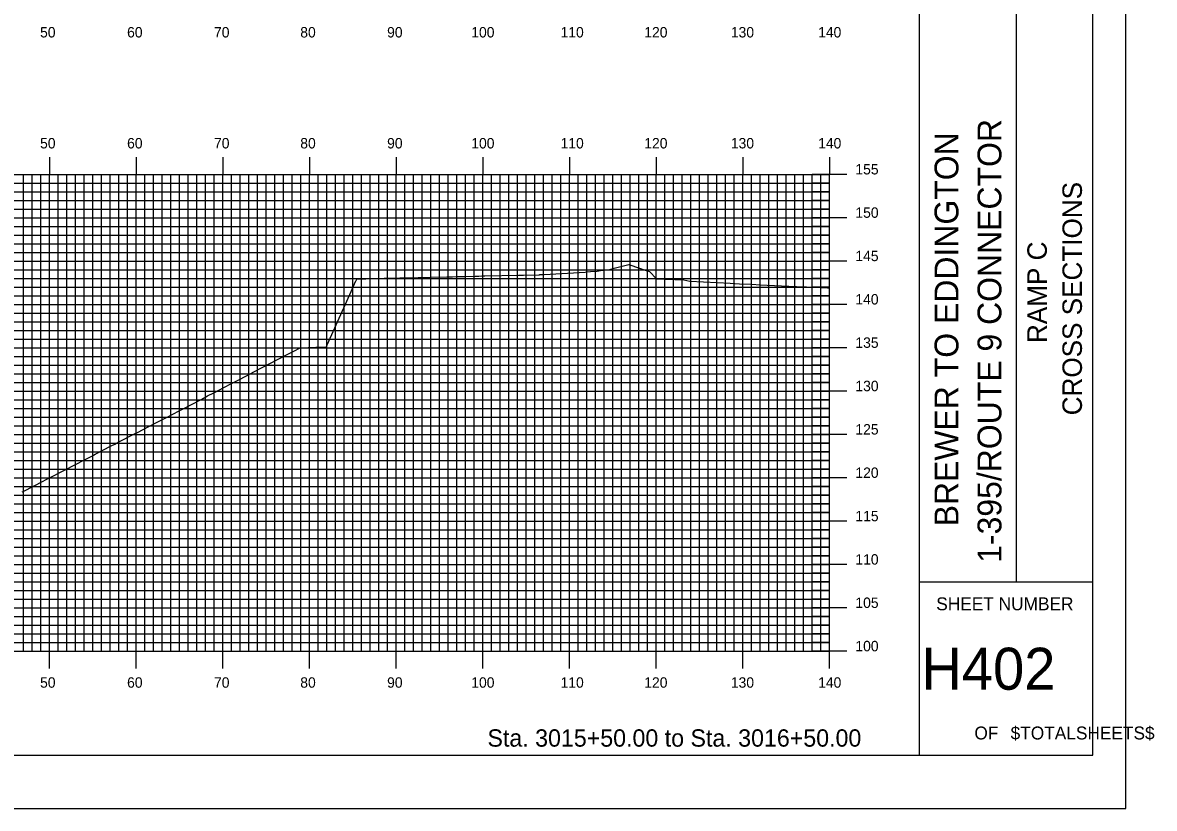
# Model space of a CAD drawing. Extents: x 1685192 to 1685536, y 461260 to 461480.
# Drawn here: x 1685405.1 to 1685535.7, y 461260 to 461350.6 of the extents above; entities that cross this region are included whole.
import ezdxf

# ---------------------------------------------------------------- set-up
doc = ezdxf.new("R2010")
doc.units = 0
for name, color, linetype in [('BORDER', 7, 'Continuous'), ('H_V ANNOTATION', 7, 'Continuous'), ('MAJOR', 7, 'Continuous'), ('MINOR', 7, 'Continuous'), ('PLOT BOUNDARY', 7, 'Continuous'), ('S_Roadway_Centerline', 7, 'Continuous')]:
    doc.layers.add(name, color=color, linetype=linetype)

msp = doc.modelspace()

# ---------------------------------------------------------------- linework, layer by layer
at = {"layer": 'BORDER'}
for p, q in [((1685508.63, 461266.07), (1685508.63, 461476.07)), ((1685519.81, 461286.08), (1685519.81, 461356.08)), ((1685508.63, 461286.08), (1685528.63, 461286.08))]:
    msp.add_line(p, q, dxfattribs=at)
msp.add_lwpolyline([(1685208.63, 461266.07), (1685528.63, 461266.07), (1685528.63, 461476.07), (1685208.63, 461476.07)], close=True, dxfattribs=at)
at = {"layer": 'MAJOR'}
for p, q in [((1685408.23, 461335.08), (1685408.23, 461333.07)), ((1685418.23, 461335.08), (1685418.23, 461333.07)), ((1685428.23, 461335.08), (1685428.23, 461333.07)), ((1685438.23, 461335.08), (1685438.23, 461333.07)), ((1685448.23, 461335.08), (1685448.23, 461333.07)), ((1685458.23, 461335.08), (1685458.23, 461333.07)), ((1685468.23, 461335.08), (1685468.23, 461333.07)), ((1685478.23, 461335.08), (1685478.23, 461333.07)), ((1685488.23, 461335.08), (1685488.23, 461333.07)), ((1685498.23, 461335.08), (1685498.23, 461333.07)), ((1685218.23, 461333.07), (1685498.23, 461333.07)), ((1685218.23, 461333.07), (1685498.23, 461333.07)), ((1685408.23, 461278.07), (1685408.23, 461333.07)), ((1685418.23, 461278.07), (1685418.23, 461333.07)), ((1685428.23, 461278.07), (1685428.23, 461333.07)), ((1685438.23, 461278.07), (1685438.23, 461333.07)), ((1685448.23, 461278.07), (1685448.23, 461333.07)), ((1685458.23, 461278.07), (1685458.23, 461333.07)), ((1685468.23, 461278.07), (1685468.23, 461333.07)), ((1685478.23, 461278.07), (1685478.23, 461333.07)), ((1685488.23, 461278.07), (1685488.23, 461333.07)), ((1685500.23, 461333.07), (1685496.23, 461333.07)), ((1685498.23, 461278.07), (1685498.23, 461333.07)), ((1685498.23, 461278.07), (1685498.23, 461333.07)), ((1685218.23, 461328.07), (1685498.23, 461328.07)), ((1685500.23, 461328.07), (1685496.23, 461328.07)), ((1685218.23, 461323.07), (1685498.23, 461323.07)), ((1685500.23, 461323.07), (1685496.23, 461323.07)), ((1685218.23, 461318.07), (1685498.23, 461318.07)), ((1685500.23, 461318.07), (1685496.23, 461318.07)), ((1685218.23, 461313.07), (1685498.23, 461313.07)), ((1685500.23, 461313.07), (1685496.23, 461313.07)), ((1685218.23, 461308.07), (1685498.23, 461308.07)), ((1685500.23, 461308.07), (1685496.23, 461308.07)), ((1685218.23, 461303.07), (1685498.23, 461303.07)), ((1685500.23, 461303.07), (1685496.23, 461303.07)), ((1685218.23, 461298.07), (1685498.23, 461298.07)), ((1685500.23, 461298.07), (1685496.23, 461298.07)), ((1685218.23, 461293.07), (1685498.23, 461293.07)), ((1685500.23, 461293.07), (1685496.23, 461293.07)), ((1685218.23, 461288.07), (1685498.23, 461288.07)), ((1685500.23, 461288.07), (1685496.23, 461288.07)), ((1685218.23, 461283.07), (1685498.23, 461283.07)), ((1685500.23, 461283.07), (1685496.23, 461283.07)), ((1685218.23, 461278.07), (1685498.23, 461278.07)), ((1685218.23, 461278.07), (1685498.23, 461278.07)), ((1685408.23, 461276.07), (1685408.23, 461278.07)), ((1685418.23, 461276.07), (1685418.23, 461278.07)), ((1685428.23, 461276.07), (1685428.23, 461278.07)), ((1685438.23, 461276.07), (1685438.23, 461278.07)), ((1685448.23, 461276.07), (1685448.23, 461278.07)), ((1685458.23, 461276.07), (1685458.23, 461278.07)), ((1685468.23, 461276.07), (1685468.23, 461278.07)), ((1685478.23, 461276.07), (1685478.23, 461278.07)), ((1685488.23, 461276.07), (1685488.23, 461278.07)), ((1685500.23, 461278.07), (1685496.23, 461278.07)), ((1685498.23, 461276.07), (1685498.23, 461278.07))]:
    msp.add_line(p, q, dxfattribs=at)
at = {"layer": 'MINOR'}
for p, q in [((1685405.23, 461278.07), (1685405.23, 461333.07)), ((1685406.23, 461278.07), (1685406.23, 461333.07)), ((1685407.23, 461278.07), (1685407.23, 461333.07)), ((1685409.23, 461278.07), (1685409.23, 461333.07)), ((1685410.23, 461278.07), (1685410.23, 461333.07)), ((1685411.23, 461278.07), (1685411.23, 461333.07)), ((1685412.23, 461278.07), (1685412.23, 461333.07)), ((1685413.23, 461278.07), (1685413.23, 461333.07)), ((1685414.23, 461278.07), (1685414.23, 461333.07)), ((1685415.23, 461278.07), (1685415.23, 461333.07)), ((1685416.23, 461278.07), (1685416.23, 461333.07)), ((1685417.23, 461278.07), (1685417.23, 461333.07)), ((1685419.23, 461278.07), (1685419.23, 461333.07)), ((1685420.23, 461278.07), (1685420.23, 461333.07)), ((1685421.23, 461278.07), (1685421.23, 461333.07)), ((1685422.23, 461278.07), (1685422.23, 461333.07)), ((1685423.23, 461278.07), (1685423.23, 461333.07)), ((1685424.23, 461278.07), (1685424.23, 461333.07)), ((1685425.23, 461278.07), (1685425.23, 461333.07)), ((1685426.23, 461278.07), (1685426.23, 461333.07)), ((1685427.23, 461278.07), (1685427.23, 461333.07)), ((1685429.23, 461278.07), (1685429.23, 461333.07)), ((1685430.23, 461278.07), (1685430.23, 461333.07)), ((1685431.23, 461278.07), (1685431.23, 461333.07)), ((1685432.23, 461278.07), (1685432.23, 461333.07)), ((1685433.23, 461278.07), (1685433.23, 461333.07)), ((1685434.23, 461278.07), (1685434.23, 461333.07)), ((1685435.23, 461278.07), (1685435.23, 461333.07)), ((1685436.23, 461278.07), (1685436.23, 461333.07)), ((1685437.23, 461278.07), (1685437.23, 461333.07)), ((1685439.23, 461278.07), (1685439.23, 461333.07)), ((1685440.23, 461278.07), (1685440.23, 461333.07)), ((1685441.23, 461278.07), (1685441.23, 461333.07)), ((1685442.23, 461278.07), (1685442.23, 461333.07)), ((1685443.23, 461278.07), (1685443.23, 461333.07)), ((1685444.23, 461278.07), (1685444.23, 461333.07)), ((1685445.23, 461278.07), (1685445.23, 461333.07)), ((1685446.23, 461278.07), (1685446.23, 461333.07)), ((1685447.23, 461278.07), (1685447.23, 461333.07)), ((1685449.23, 461278.07), (1685449.23, 461333.07)), ((1685450.23, 461278.07), (1685450.23, 461333.07)), ((1685451.23, 461278.07), (1685451.23, 461333.07)), ((1685452.23, 461278.07), (1685452.23, 461333.07)), ((1685453.23, 461278.07), (1685453.23, 461333.07)), ((1685454.23, 461278.07), (1685454.23, 461333.07)), ((1685455.23, 461278.07), (1685455.23, 461333.07)), ((1685456.23, 461278.07), (1685456.23, 461333.07)), ((1685457.23, 461278.07), (1685457.23, 461333.07)), ((1685459.23, 461278.07), (1685459.23, 461333.07)), ((1685460.23, 461278.07), (1685460.23, 461333.07)), ((1685461.23, 461278.07), (1685461.23, 461333.07)), ((1685462.23, 461278.07), (1685462.23, 461333.07)), ((1685463.23, 461278.07), (1685463.23, 461333.07)), ((1685464.23, 461278.07), (1685464.23, 461333.07)), ((1685465.23, 461278.07), (1685465.23, 461333.07)), ((1685466.23, 461278.07), (1685466.23, 461333.07)), ((1685467.23, 461278.07), (1685467.23, 461333.07)), ((1685469.23, 461278.07), (1685469.23, 461333.07)), ((1685470.23, 461278.07), (1685470.23, 461333.07)), ((1685471.23, 461278.07), (1685471.23, 461333.07)), ((1685472.23, 461278.07), (1685472.23, 461333.07)), ((1685473.23, 461278.07), (1685473.23, 461333.07)), ((1685474.23, 461278.07), (1685474.23, 461333.07)), ((1685475.23, 461278.07), (1685475.23, 461333.07)), ((1685476.23, 461278.07), (1685476.23, 461333.07)), ((1685477.23, 461278.07), (1685477.23, 461333.07)), ((1685479.23, 461278.07), (1685479.23, 461333.07)), ((1685480.23, 461278.07), (1685480.23, 461333.07)), ((1685481.23, 461278.07), (1685481.23, 461333.07)), ((1685482.23, 461278.07), (1685482.23, 461333.07)), ((1685483.23, 461278.07), (1685483.23, 461333.07)), ((1685484.23, 461278.07), (1685484.23, 461333.07)), ((1685485.23, 461278.07), (1685485.23, 461333.07)), ((1685486.23, 461278.07), (1685486.23, 461333.07)), ((1685487.23, 461278.07), (1685487.23, 461333.07)), ((1685489.23, 461278.07), (1685489.23, 461333.07)), ((1685490.23, 461278.07), (1685490.23, 461333.07)), ((1685491.23, 461278.07), (1685491.23, 461333.07)), ((1685492.23, 461278.07), (1685492.23, 461333.07)), ((1685493.23, 461278.07), (1685493.23, 461333.07)), ((1685494.23, 461278.07), (1685494.23, 461333.07)), ((1685495.23, 461278.07), (1685495.23, 461333.07)), ((1685496.23, 461278.07), (1685496.23, 461333.07)), ((1685497.23, 461278.07), (1685497.23, 461333.07)), ((1685218.23, 461332.07), (1685498.23, 461332.07)), ((1685218.23, 461331.07), (1685498.23, 461331.07)), ((1685498.23, 461332.07), (1685496.23, 461332.07)), ((1685498.23, 461331.07), (1685496.23, 461331.07)), ((1685218.23, 461330.07), (1685498.23, 461330.07)), ((1685498.23, 461330.07), (1685496.23, 461330.07)), ((1685218.23, 461329.07), (1685498.23, 461329.07)), ((1685498.23, 461329.07), (1685496.23, 461329.07)), ((1685218.23, 461327.07), (1685498.23, 461327.07)), ((1685498.23, 461327.07), (1685496.23, 461327.07)), ((1685218.23, 461326.07), (1685498.23, 461326.07)), ((1685498.23, 461326.07), (1685496.23, 461326.07)), ((1685218.23, 461325.07), (1685498.23, 461325.07)), ((1685498.23, 461325.07), (1685496.23, 461325.07)), ((1685218.23, 461324.07), (1685498.23, 461324.07)), ((1685498.23, 461324.07), (1685496.23, 461324.07)), ((1685218.23, 461322.07), (1685498.23, 461322.07)), ((1685498.23, 461322.07), (1685496.23, 461322.07)), ((1685218.23, 461321.07), (1685498.23, 461321.07)), ((1685498.23, 461321.07), (1685496.23, 461321.07)), ((1685218.23, 461320.07), (1685498.23, 461320.07)), ((1685498.23, 461320.07), (1685496.23, 461320.07)), ((1685218.23, 461319.07), (1685498.23, 461319.07)), ((1685498.23, 461319.07), (1685496.23, 461319.07)), ((1685218.23, 461317.07), (1685498.23, 461317.07)), ((1685498.23, 461317.07), (1685496.23, 461317.07)), ((1685218.23, 461316.07), (1685498.23, 461316.07)), ((1685498.23, 461316.07), (1685496.23, 461316.07)), ((1685218.23, 461315.07), (1685498.23, 461315.07)), ((1685218.23, 461314.07), (1685498.23, 461314.07)), ((1685498.23, 461315.07), (1685496.23, 461315.07)), ((1685498.23, 461314.07), (1685496.23, 461314.07)), ((1685218.23, 461312.07), (1685498.23, 461312.07)), ((1685498.23, 461312.07), (1685496.23, 461312.07)), ((1685218.23, 461311.07), (1685498.23, 461311.07)), ((1685218.23, 461310.07), (1685498.23, 461310.07)), ((1685498.23, 461311.07), (1685496.23, 461311.07)), ((1685498.23, 461310.07), (1685496.23, 461310.07)), ((1685218.23, 461309.07), (1685498.23, 461309.07)), ((1685498.23, 461309.07), (1685496.23, 461309.07)), ((1685218.23, 461307.07), (1685498.23, 461307.07)), ((1685218.23, 461306.07), (1685498.23, 461306.07)), ((1685498.23, 461307.07), (1685496.23, 461307.07)), ((1685498.23, 461306.07), (1685496.23, 461306.07)), ((1685218.23, 461305.07), (1685498.23, 461305.07)), ((1685498.23, 461305.07), (1685496.23, 461305.07)), ((1685218.23, 461304.07), (1685498.23, 461304.07)), ((1685498.23, 461304.07), (1685496.23, 461304.07)), ((1685218.23, 461302.07), (1685498.23, 461302.07)), ((1685218.23, 461301.07), (1685498.23, 461301.07)), ((1685498.23, 461302.07), (1685496.23, 461302.07)), ((1685498.23, 461301.07), (1685496.23, 461301.07)), ((1685218.23, 461300.07), (1685498.23, 461300.07)), ((1685498.23, 461300.07), (1685496.23, 461300.07)), ((1685218.23, 461299.07), (1685498.23, 461299.07)), ((1685498.23, 461299.07), (1685496.23, 461299.07)), ((1685218.23, 461297.07), (1685498.23, 461297.07)), ((1685498.23, 461297.07), (1685496.23, 461297.07)), ((1685218.23, 461296.07), (1685498.23, 461296.07)), ((1685498.23, 461296.07), (1685496.23, 461296.07)), ((1685218.23, 461295.07), (1685498.23, 461295.07)), ((1685498.23, 461295.07), (1685496.23, 461295.07)), ((1685218.23, 461294.07), (1685498.23, 461294.07)), ((1685498.23, 461294.07), (1685496.23, 461294.07)), ((1685218.23, 461292.07), (1685498.23, 461292.07)), ((1685498.23, 461292.07), (1685496.23, 461292.07)), ((1685218.23, 461291.07), (1685498.23, 461291.07)), ((1685498.23, 461291.07), (1685496.23, 461291.07)), ((1685218.23, 461290.07), (1685498.23, 461290.07)), ((1685498.23, 461290.07), (1685496.23, 461290.07)), ((1685218.23, 461289.07), (1685498.23, 461289.07)), ((1685498.23, 461289.07), (1685496.23, 461289.07)), ((1685218.23, 461287.07), (1685498.23, 461287.07)), ((1685498.23, 461287.07), (1685496.23, 461287.07)), ((1685218.23, 461286.07), (1685498.23, 461286.07)), ((1685498.23, 461286.07), (1685496.23, 461286.07)), ((1685218.23, 461285.07), (1685498.23, 461285.07)), ((1685218.23, 461284.07), (1685498.23, 461284.07)), ((1685498.23, 461285.07), (1685496.23, 461285.07)), ((1685498.23, 461284.07), (1685496.23, 461284.07)), ((1685218.23, 461282.07), (1685498.23, 461282.07)), ((1685498.23, 461282.07), (1685496.23, 461282.07)), ((1685218.23, 461281.07), (1685498.23, 461281.07)), ((1685218.23, 461280.07), (1685498.23, 461280.07)), ((1685498.23, 461281.07), (1685496.23, 461281.07)), ((1685498.23, 461280.07), (1685496.23, 461280.07)), ((1685218.23, 461279.07), (1685498.23, 461279.07)), ((1685498.23, 461279.07), (1685496.23, 461279.07))]:
    msp.add_line(p, q, dxfattribs=at)
at = {"layer": 'PLOT BOUNDARY'}
msp.add_lwpolyline([(1685192.44, 461259.95), (1685532.44, 461259.95), (1685532.44, 461479.95), (1685192.44, 461479.95)], close=True, dxfattribs=at)
at = {"layer": 'S_Roadway_Centerline'}
msp.add_lwpolyline([(1685405.09, 461296.45), (1685405.27, 461296.54), (1685407.53, 461297.7), (1685407.77, 461297.83), (1685408.02, 461297.96), (1685410.14, 461299.05), (1685410.44, 461299.21), (1685410.77, 461299.37), (1685412.75, 461300.4), (1685413.12, 461300.59), (1685413.51, 461300.79), (1685415.36, 461301.75), (1685415.8, 461301.97), (1685416.25, 461302.21), (1685417.97, 461303.1), (1685418.47, 461303.36), (1685418.99, 461303.63), (1685420.59, 461304.45), (1685421.14, 461304.74), (1685421.73, 461305.04), (1685423.2, 461305.81), (1685423.82, 461306.13), (1685424.46, 461306.46), (1685425.82, 461307.16), (1685426.49, 461307.52), (1685427.19, 461307.88), (1685428.43, 461308.52), (1685429.16, 461308.9), (1685429.93, 461309.3), (1685431.05, 461309.88), (1685431.83, 461310.29), (1685435.6, 461312.25), (1685436.43, 461312.69), (1685437.18, 461313.07), (1685438.99, 461313.13), (1685440.19, 461313.17), (1685440.26, 461313.32), (1685440.29, 461313.4), (1685442.9, 461319.21), (1685443.61, 461320.79), (1685443.64, 461320.85), (1685443.71, 461321.01), (1685443.87, 461321.02), (1685444.76, 461321.04), (1685445.14, 461321.05), (1685445.79, 461321.06), (1685445.94, 461321.07), (1685446.86, 461321.09), (1685447.81, 461321.11), (1685448.67, 461321.13), (1685449.14, 461321.14), (1685450.01, 461321.16), (1685450.8, 461321.18), (1685451.5, 461321.2), (1685452.15, 461321.21), (1685454.09, 461321.26), (1685454.73, 461321.27), (1685455.3, 461321.29), (1685455.82, 461321.3), (1685456.04, 461321.31), (1685456.28, 461321.31), (1685457.37, 461321.34), (1685457.78, 461321.35), (1685458.14, 461321.36), (1685458.47, 461321.36), (1685462.37, 461321.46), (1685462.53, 461321.46), (1685462.68, 461321.46), (1685462.81, 461321.47), (1685462.93, 461321.47), (1685464.72, 461321.51), (1685464.75, 461321.51), (1685464.78, 461321.51), (1685464.8, 461321.51), (1685464.82, 461321.52), (1685465.31, 461321.53), (1685470.05, 461321.8), (1685470.22, 461321.83), (1685470.66, 461321.86), (1685471.42, 461321.9), (1685471.84, 461322), (1685472.77, 461322.06), (1685473.41, 461322.25), (1685475.08, 461322.68), (1685475.33, 461322.59), (1685476.98, 461322.03), (1685477.49, 461321.88), (1685478.27, 461321.04), (1685481.45, 461320.91), (1685482.14, 461320.75), (1685485.27, 461320.59), (1685486.77, 461320.52), (1685487.84, 461320.47), (1685489.27, 461320.4), (1685490.23, 461320.35), (1685492.71, 461320.23), (1685494.44, 461320.15), (1685495.6, 461320.09), (1685498.02, 461319.98), (1685498.23, 461319.97)], dxfattribs=at)

# ---------------------------------------------------------------- texts
at = {"layer": 'BORDER'}
for s, height, p in [('1-395/ROUTE 9 CONNECTOR', 2.7557, (1685518.08, 461288.27)), ('BREWER TO EDDINGTON', 2.7557, (1685513.12, 461292.48)), ('CROSS SECTIONS', 2.25, (1685527.37, 461305.29)), ('RAMP C', 2.25, (1685523.32, 461313.63))]:
    msp.add_text(s, height=height, rotation=90, dxfattribs=at).set_placement(p)
for s, height, p in [('SHEET NUMBER', 1.4905, (1685510.56, 461282.8)), ('H402', 4.839, (1685508.84, 461273.64)), ('$TOTALSHEETS$', 1.4905, (1685519.14, 461267.9)), ('OF', 1.491, (1685514.96, 461267.9))]:
    msp.add_text(s, height=height, dxfattribs=at).set_placement(p)
at = {"layer": 'H_V ANNOTATION'}
for s, height, p in [('50', 1.2, (1685407.16, 461348.87)), ('60', 1.2, (1685417.2, 461348.87)), ('70', 1.2, (1685427.23, 461348.87)), ('80', 1.2, (1685437.18, 461348.87)), ('90', 1.2, (1685447.2, 461348.87)), ('100', 1.2, (1685456.91, 461348.87)), ('110', 1.2, (1685467.21, 461348.87)), ('120', 1.2, (1685476.87, 461348.87)), ('130', 1.2, (1685486.86, 461348.87)), ('140', 1.2, (1685496.93, 461348.87)), ('50', 1.2, (1685407.16, 461336.07)), ('60', 1.2, (1685417.2, 461336.07)), ('70', 1.2, (1685427.23, 461336.07)), ('80', 1.2, (1685437.18, 461336.07)), ('90', 1.2, (1685447.2, 461336.07)), ('100', 1.2, (1685456.91, 461336.07)), ('110', 1.2, (1685467.21, 461336.07)), ('120', 1.2, (1685476.87, 461336.07)), ('130', 1.2, (1685486.86, 461336.07)), ('140', 1.2, (1685496.93, 461336.07)), ('155', 1.2, (1685501.23, 461333.07)), ('150', 1.2, (1685501.23, 461328.07)), ('145', 1.2, (1685501.23, 461323.07)), ('140', 1.2, (1685501.23, 461318.07)), ('135', 1.2, (1685501.23, 461313.07)), ('130', 1.2, (1685501.23, 461308.07)), ('125', 1.2, (1685501.23, 461303.07)), ('120', 1.2, (1685501.23, 461298.07)), ('115', 1.2, (1685501.23, 461293.07)), ('110', 1.2, (1685501.23, 461288.07)), ('105', 1.2, (1685501.23, 461283.07)), ('100', 1.2, (1685501.23, 461278.07)), ('50', 1.2, (1685407.16, 461273.87)), ('60', 1.2, (1685417.2, 461273.87)), ('70', 1.2, (1685427.23, 461273.87)), ('80', 1.2, (1685437.18, 461273.87)), ('90', 1.2, (1685447.2, 461273.87)), ('100', 1.2, (1685456.91, 461273.87)), ('110', 1.2, (1685467.21, 461273.87)), ('120', 1.2, (1685476.87, 461273.87)), ('130', 1.2, (1685486.86, 461273.87)), ('140', 1.2, (1685496.93, 461273.87)), ('Sta. 3015+50.00 to Sta. 3016+50.00', 2.0004, (1685458.78, 461267.07))]:
    msp.add_text(s, height=height, dxfattribs=at).set_placement(p)

doc.saveas('drawing.dxf')
